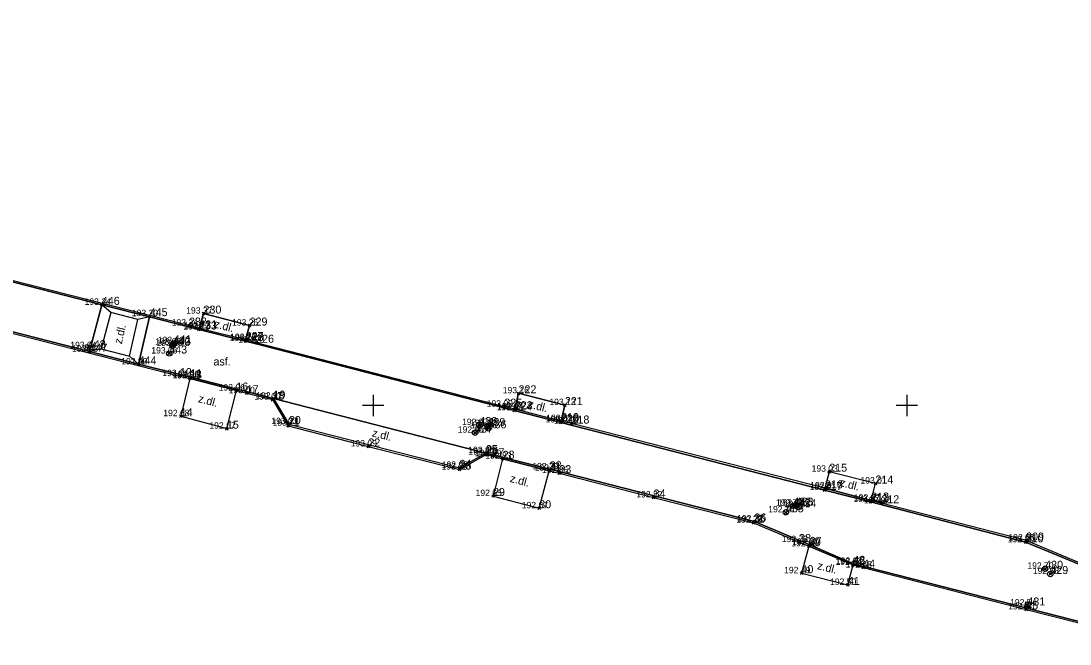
# Model space of a CAD drawing. Extents: x -706861 to -706379, y -1036456 to -1036201.
# Drawn here: x -706633 to -706534.7, y -1036372.3 to -1036314 of the extents above; entities that cross this region are included whole.
import ezdxf

# ---------------------------------------------------------------- set-up
doc = ezdxf.new("R2010")
doc.units = 0
for name, color, linetype in [('18_popisy', 7, 'Continuous'), ('29_vodovod', 7, 'Continuous'), ('30_kanalizace splašková', 7, 'Continuous'), ('40_plochy', 7, 'Continuous'), ('51_body polohopisu_značky', 7, 'Continuous'), ('52_body polohopisu_čísla', 7, 'Continuous'), ('53_body polohopisu_výšky', 7, 'Continuous'), ('54_body polohopisu_čísla nadbytečné pro kreslení', 7, 'Continuous'), ('5_rozhraní ploch', 7, 'Continuous'), ('60_mapový rám_legenda', 7, 'Continuous')]:
    doc.layers.add(name, color=color, linetype=linetype)

msp = doc.modelspace()

# ---------------------------------------------------------------- linework, layer by layer
at = {"layer": '29_vodovod'}
for centre in [(-706618.79, -1036344.42), (-706618.67, -1036344.15), (-706590.05, -1036351.82), (-706589.29, -1036351.91), (-706560.65, -1036359.38), (-706560.43, -1036359.38), (-706537.05, -1036365.29)]:
    msp.add_circle(centre, 0.25, dxfattribs=at)
at = {"layer": '30_kanalizace splašková'}
for p, q in [((-706626.661, -1036344.377), (-706626.779, -1036344.863)), ((-706538.657, -1036368.488), (-706538.783, -1036368.972))]:
    msp.add_line(p, q, dxfattribs=at)
for points in [[(-706626.904, -1036344.318), (-706627.023, -1036344.804), (-706626.536, -1036344.923), (-706626.417, -1036344.437)], [(-706538.9, -1036368.425), (-706539.026, -1036368.909), (-706538.54, -1036369.035), (-706538.415, -1036368.551)]]:
    msp.add_lwpolyline(points, close=True, dxfattribs=at)
for centre in [(-706618.78, -1036344.3), (-706619.1, -1036345.12), (-706590.45, -1036352.54), (-706589.19, -1036352.13), (-706560.15, -1036359.52), (-706561.34, -1036360), (-706536.57, -1036365.78)]:
    msp.add_circle(centre, 0.25, dxfattribs=at)
at = {"layer": '40_plochy'}
for points in [[(-706673.91, -1036328.1), (-706669.56, -1036329.23), (-706644.87, -1036335.59), (-706640.53, -1036336.68), (-706625.407, -1036340.547), (-706626.555, -1036344.932), (-706641.34, -1036341.16), (-706645.7, -1036340.05), (-706670.86, -1036333.6), (-706675.27, -1036332.47)], [(-706625.407, -1036340.547), (-706620.945, -1036341.687), (-706621.962, -1036346.105), (-706626.555, -1036344.932)], [(-706615.89, -1036341.38), (-706611.57, -1036342.5), (-706611.94, -1036343.85), (-706616.28, -1036342.77)], [(-706617.16, -1036347.46), (-706618.02, -1036350.99), (-706613.7, -1036352.16), (-706612.81, -1036348.59)], [(-706609.33, -1036349.34), (-706607.89, -1036351.73), (-706591.92, -1036355.83), (-706589.44, -1036354.45)], [(-706586.38, -1036348.85), (-706582.04, -1036349.95), (-706582.39, -1036351.45), (-706586.73, -1036350.34)], [(-706587.87, -1036354.98), (-706588.77, -1036358.47), (-706584.44, -1036359.62), (-706583.5, -1036356.1)], [(-706557.28, -1036356.19), (-706557.68, -1036357.75), (-706553.35, -1036358.9), (-706552.95, -1036357.3)], [(-706559.18, -1036363.18), (-706559.88, -1036365.71), (-706555.53, -1036366.8), (-706555.05, -1036364.92)]]:
    msp.add_lwpolyline(points, close=True, dxfattribs=at)
msp.add_lwpolyline([(-706530.33, -1036371.14), (-706555.02, -1036364.83), (-706559.11, -1036363.05), (-706564.29, -1036360.86), (-706583.46, -1036355.97), (-706589.44, -1036354.45), (-706609.33, -1036349.34), (-706617.12, -1036347.34), (-706621.962, -1036346.105), (-706620.945, -1036341.687), (-706616.32, -1036342.87), (-706611.97, -1036343.95), (-706610.97, -1036344.21), (-706586.78, -1036350.45), (-706582.43, -1036351.58), (-706557.72, -1036357.91), (-706553.4, -1036359.02), (-706538.88, -1036362.81), (-706529.64, -1036366.62)], dxfattribs=at)
at = {"layer": '51_body polohopisu_značky'}
for points in [[(-706625.53, -1036340.68), (-706625.29, -1036340.44)], [(-706625.53, -1036340.44), (-706625.29, -1036340.68)], [(-706621.05, -1036341.74), (-706620.81, -1036341.5)], [(-706621.05, -1036341.5), (-706620.81, -1036341.74)], [(-706616.01, -1036341.5), (-706615.77, -1036341.26)], [(-706616.01, -1036341.26), (-706615.77, -1036341.5)], [(-706617.37, -1036342.62), (-706617.13, -1036342.38)], [(-706617.37, -1036342.38), (-706617.13, -1036342.62)], [(-706611.69, -1036342.62), (-706611.45, -1036342.38)], [(-706611.69, -1036342.38), (-706611.45, -1036342.62)], [(-706616.44, -1036342.99), (-706616.2, -1036342.75)], [(-706616.44, -1036342.75), (-706616.2, -1036342.99)], [(-706616.4, -1036342.89), (-706616.16, -1036342.65)], [(-706616.4, -1036342.65), (-706616.16, -1036342.89)], [(-706626.84, -1036344.74), (-706626.6, -1036344.5)], [(-706626.84, -1036344.5), (-706626.6, -1036344.74)], [(-706618.91, -1036344.54), (-706618.67, -1036344.3)], [(-706618.91, -1036344.3), (-706618.67, -1036344.54)], [(-706618.9, -1036344.42), (-706618.66, -1036344.18)], [(-706618.9, -1036344.18), (-706618.66, -1036344.42)], [(-706618.79, -1036344.27), (-706618.55, -1036344.03)], [(-706618.79, -1036344.03), (-706618.55, -1036344.27)], [(-706612.06, -1036343.97), (-706611.82, -1036343.73)], [(-706612.06, -1036343.73), (-706611.82, -1036343.97)], [(-706612.06, -1036344.07), (-706611.82, -1036343.83)], [(-706612.06, -1036343.83), (-706611.82, -1036344.07)], [(-706611.08, -1036344.23), (-706610.84, -1036343.99)], [(-706611.08, -1036343.99), (-706610.84, -1036344.23)], [(-706626.68, -1036345.07), (-706626.44, -1036344.83)], [(-706626.68, -1036344.83), (-706626.44, -1036345.07)], [(-706619.22, -1036345.24), (-706618.98, -1036345)], [(-706619.22, -1036345), (-706618.98, -1036345.24)], [(-706622.09, -1036346.26), (-706621.85, -1036346.02)], [(-706622.09, -1036346.02), (-706621.85, -1036346.26)], [(-706618.22, -1036347.36), (-706617.98, -1036347.12)], [(-706618.22, -1036347.12), (-706617.98, -1036347.36)], [(-706617.28, -1036347.58), (-706617.04, -1036347.34)], [(-706617.28, -1036347.34), (-706617.04, -1036347.58)], [(-706617.24, -1036347.46), (-706617, -1036347.22)], [(-706617.24, -1036347.22), (-706617, -1036347.46)], [(-706612.93, -1036348.71), (-706612.69, -1036348.47)], [(-706612.93, -1036348.47), (-706612.69, -1036348.71)], [(-706611.96, -1036348.96), (-706611.72, -1036348.72)], [(-706611.96, -1036348.72), (-706611.72, -1036348.96)], [(-706609.54, -1036349.56), (-706609.3, -1036349.32)], [(-706609.54, -1036349.32), (-706609.3, -1036349.56)], [(-706609.45, -1036349.46), (-706609.21, -1036349.22)], [(-706609.45, -1036349.22), (-706609.21, -1036349.46)], [(-706586.5, -1036348.97), (-706586.26, -1036348.73)], [(-706586.5, -1036348.73), (-706586.26, -1036348.97)], [(-706587.83, -1036350.22), (-706587.59, -1036349.98)], [(-706587.83, -1036349.98), (-706587.59, -1036350.22)], [(-706586.9, -1036350.57), (-706586.66, -1036350.33)], [(-706586.9, -1036350.33), (-706586.66, -1036350.57)], [(-706586.85, -1036350.46), (-706586.61, -1036350.22)], [(-706586.85, -1036350.22), (-706586.61, -1036350.46)], [(-706582.16, -1036350.07), (-706581.92, -1036349.83)], [(-706582.16, -1036349.83), (-706581.92, -1036350.07)], [(-706618.14, -1036351.11), (-706617.9, -1036350.87)], [(-706618.14, -1036350.87), (-706617.9, -1036351.11)], [(-706582.51, -1036351.57), (-706582.27, -1036351.33)], [(-706582.51, -1036351.33), (-706582.27, -1036351.57)], [(-706613.82, -1036352.28), (-706613.58, -1036352.04)], [(-706613.82, -1036352.04), (-706613.58, -1036352.28)], [(-706608.09, -1036352.01), (-706607.85, -1036351.77)], [(-706608.09, -1036351.77), (-706607.85, -1036352.01)], [(-706608.01, -1036351.85), (-706607.77, -1036351.61)], [(-706608.01, -1036351.61), (-706607.77, -1036351.85)], [(-706590.57, -1036352.66), (-706590.33, -1036352.42)], [(-706590.57, -1036352.42), (-706590.33, -1036352.66)], [(-706590.17, -1036351.94), (-706589.93, -1036351.7)], [(-706590.17, -1036351.7), (-706589.93, -1036351.94)], [(-706589.41, -1036352.03), (-706589.17, -1036351.79)], [(-706589.41, -1036351.79), (-706589.17, -1036352.03)], [(-706589.31, -1036352.25), (-706589.07, -1036352.01)], [(-706589.31, -1036352.01), (-706589.07, -1036352.25)], [(-706582.55, -1036351.7), (-706582.31, -1036351.46)], [(-706582.55, -1036351.46), (-706582.31, -1036351.7)], [(-706581.54, -1036351.8), (-706581.3, -1036351.56)], [(-706581.54, -1036351.56), (-706581.3, -1036351.8)], [(-706600.57, -1036353.95), (-706600.33, -1036353.71)], [(-706600.57, -1036353.71), (-706600.33, -1036353.95)], [(-706589.56, -1036354.57), (-706589.32, -1036354.33)], [(-706589.56, -1036354.33), (-706589.32, -1036354.57)], [(-706589.52, -1036354.71), (-706589.28, -1036354.47)], [(-706589.52, -1036354.47), (-706589.28, -1036354.71)], [(-706588.94, -1036354.86), (-706588.7, -1036354.62)], [(-706588.94, -1036354.62), (-706588.7, -1036354.86)], [(-706587.99, -1036355.1), (-706587.75, -1036354.86)], [(-706587.99, -1036354.86), (-706587.75, -1036355.1)], [(-706592.04, -1036355.95), (-706591.8, -1036355.71)], [(-706592.04, -1036355.71), (-706591.8, -1036355.95)], [(-706592.03, -1036356.11), (-706591.79, -1036355.87)], [(-706592.03, -1036355.87), (-706591.79, -1036356.11)], [(-706583.62, -1036356.22), (-706583.38, -1036355.98)], [(-706583.62, -1036355.98), (-706583.38, -1036356.22)], [(-706583.58, -1036356.09), (-706583.34, -1036355.85)], [(-706583.58, -1036355.85), (-706583.34, -1036356.09)], [(-706582.68, -1036356.45), (-706582.44, -1036356.21)], [(-706582.68, -1036356.21), (-706582.44, -1036356.45)], [(-706557.4, -1036356.31), (-706557.16, -1036356.07)], [(-706557.4, -1036356.07), (-706557.16, -1036356.31)], [(-706553.07, -1036357.42), (-706552.83, -1036357.18)], [(-706553.07, -1036357.18), (-706552.83, -1036357.42)], [(-706557.84, -1036358.03), (-706557.6, -1036357.79)], [(-706557.84, -1036357.79), (-706557.6, -1036358.03)], [(-706557.8, -1036357.87), (-706557.56, -1036357.63)], [(-706557.8, -1036357.63), (-706557.56, -1036357.87)], [(-706588.89, -1036358.59), (-706588.65, -1036358.35)], [(-706588.89, -1036358.35), (-706588.65, -1036358.59)], [(-706573.85, -1036358.73), (-706573.61, -1036358.49)], [(-706573.85, -1036358.49), (-706573.61, -1036358.73)], [(-706560.77, -1036359.5), (-706560.53, -1036359.26)], [(-706560.77, -1036359.26), (-706560.53, -1036359.5)], [(-706560.55, -1036359.5), (-706560.31, -1036359.26)], [(-706560.55, -1036359.26), (-706560.31, -1036359.5)], [(-706553.52, -1036359.14), (-706553.28, -1036358.9)], [(-706553.52, -1036358.9), (-706553.28, -1036359.14)], [(-706553.47, -1036359.02), (-706553.23, -1036358.78)], [(-706553.47, -1036358.78), (-706553.23, -1036359.02)], [(-706552.52, -1036359.27), (-706552.28, -1036359.03)], [(-706552.52, -1036359.03), (-706552.28, -1036359.27)], [(-706584.56, -1036359.74), (-706584.32, -1036359.5)], [(-706584.56, -1036359.5), (-706584.32, -1036359.74)], [(-706561.46, -1036360.12), (-706561.22, -1036359.88)], [(-706561.46, -1036359.88), (-706561.22, -1036360.12)], [(-706560.27, -1036359.64), (-706560.03, -1036359.4)], [(-706560.27, -1036359.4), (-706560.03, -1036359.64)], [(-706564.49, -1036361.09), (-706564.25, -1036360.85)], [(-706564.49, -1036360.85), (-706564.25, -1036361.09)], [(-706564.41, -1036360.98), (-706564.17, -1036360.74)], [(-706564.41, -1036360.74), (-706564.17, -1036360.98)], [(-706560.22, -1036362.91), (-706559.98, -1036362.67)], [(-706560.22, -1036362.67), (-706559.98, -1036362.91)], [(-706559.3, -1036363.3), (-706559.06, -1036363.06)], [(-706559.3, -1036363.06), (-706559.06, -1036363.3)], [(-706559.23, -1036363.17), (-706558.99, -1036362.93)], [(-706559.23, -1036362.93), (-706558.99, -1036363.17)], [(-706539, -1036362.93), (-706538.76, -1036362.69)], [(-706539, -1036362.69), (-706538.76, -1036362.93)], [(-706538.96, -1036362.76), (-706538.72, -1036362.52)], [(-706538.96, -1036362.52), (-706538.72, -1036362.76)], [(-706555.17, -1036365.04), (-706554.93, -1036364.8)], [(-706555.17, -1036364.8), (-706554.93, -1036365.04)], [(-706555.14, -1036364.95), (-706554.9, -1036364.71)], [(-706555.14, -1036364.71), (-706554.9, -1036364.95)], [(-706554.22, -1036365.29), (-706553.98, -1036365.05)], [(-706554.22, -1036365.05), (-706553.98, -1036365.29)], [(-706537.17, -1036365.41), (-706536.93, -1036365.17)], [(-706537.17, -1036365.17), (-706536.93, -1036365.41)], [(-706560, -1036365.83), (-706559.76, -1036365.59)], [(-706560, -1036365.59), (-706559.76, -1036365.83)], [(-706536.69, -1036365.9), (-706536.45, -1036365.66)], [(-706536.69, -1036365.66), (-706536.45, -1036365.9)], [(-706555.65, -1036366.92), (-706555.41, -1036366.68)], [(-706555.65, -1036366.68), (-706555.41, -1036366.92)], [(-706538.95, -1036369.22), (-706538.71, -1036368.98)], [(-706538.95, -1036368.98), (-706538.71, -1036369.22)], [(-706538.84, -1036368.85), (-706538.6, -1036368.61)], [(-706538.84, -1036368.61), (-706538.6, -1036368.85)]]:
    msp.add_lwpolyline(points, dxfattribs=at)
at = {"layer": '5_rozhraní ploch'}
for p, q in [((-706624.564, -1036341.278), (-706625.407, -1036340.547)), ((-706620.945, -1036341.687), (-706622.027, -1036341.927)), ((-706625.46, -1036344.696), (-706626.555, -1036344.932)), ((-706622.819, -1036345.37), (-706621.962, -1036346.105))]:
    msp.add_line(p, q, dxfattribs=at)
for points in [[(-706611.97, -1036343.95), (-706616.32, -1036342.87), (-706620.945, -1036341.687), (-706625.407, -1036340.547), (-706640.53, -1036336.68), (-706644.87, -1036335.59), (-706669.56, -1036329.23), (-706673.91, -1036328.1), (-706684.54, -1036325.41), (-706703.07, -1036320.63), (-706706.65, -1036319.75), (-706716.69, -1036318.74), (-706728.29, -1036315.81), (-706732.59, -1036314.76), (-706736.58, -1036313.96)], [(-706670.86, -1036333.6), (-706654.96, -1036337.67), (-706645.7, -1036340.05), (-706641.34, -1036341.16), (-706626.555, -1036344.932), (-706621.962, -1036346.105), (-706617.12, -1036347.34), (-706609.33, -1036349.34), (-706607.89, -1036351.73), (-706591.92, -1036355.83), (-706589.44, -1036354.45), (-706583.46, -1036355.97), (-706564.29, -1036360.86), (-706559.11, -1036363.05), (-706555.02, -1036364.83), (-706530.33, -1036371.14), (-706525.95, -1036372.11), (-706524.99, -1036372.34)], [(-706518.9, -1036367), (-706521.32, -1036368.51), (-706525.29, -1036367.55), (-706529.63, -1036366.53), (-706530.5, -1036366.13), (-706538.84, -1036362.64), (-706552.4, -1036359.15), (-706553.35, -1036358.9), (-706557.68, -1036357.75), (-706581.42, -1036351.68), (-706582.39, -1036351.45), (-706586.73, -1036350.34), (-706587.71, -1036350.1), (-706610.95, -1036344.11), (-706611.94, -1036343.85), (-706616.28, -1036342.77), (-706617.25, -1036342.5), (-706639.52, -1036336.83)], [(-706625.407, -1036340.547), (-706626.555, -1036344.932)], [(-706640.42, -1036341.53), (-706618.1, -1036347.24), (-706617.16, -1036347.46), (-706612.81, -1036348.59), (-706611.84, -1036348.84), (-706609.42, -1036349.44), (-706607.97, -1036351.89), (-706600.45, -1036353.83), (-706591.91, -1036355.99), (-706589.4, -1036354.59), (-706588.82, -1036354.74), (-706587.87, -1036354.98), (-706583.5, -1036356.1), (-706582.56, -1036356.33), (-706573.73, -1036358.61), (-706564.37, -1036360.97), (-706560.1, -1036362.79), (-706559.18, -1036363.18), (-706555.05, -1036364.92), (-706554.1, -1036365.17), (-706538.83, -1036369.1), (-706531.32, -1036371.01)], [(-706624.564, -1036341.278), (-706625.46, -1036344.696)], [(-706622.027, -1036341.927), (-706624.564, -1036341.278)], [(-706611.94, -1036343.85), (-706611.57, -1036342.5), (-706615.89, -1036341.38), (-706616.28, -1036342.77)], [(-706622.819, -1036345.37), (-706622.027, -1036341.927)], [(-706621.962, -1036346.105), (-706620.945, -1036341.687)], [(-706518.86, -1036367.15), (-706521.26, -1036368.67), (-706525.27, -1036367.7), (-706529.64, -1036366.62), (-706538.88, -1036362.81), (-706553.4, -1036359.02), (-706557.72, -1036357.91), (-706582.43, -1036351.58), (-706586.78, -1036350.45), (-706610.97, -1036344.21), (-706611.97, -1036343.95)], [(-706625.46, -1036344.696), (-706622.819, -1036345.37)], [(-706617.16, -1036347.46), (-706618.02, -1036350.99), (-706613.7, -1036352.16), (-706612.81, -1036348.59)], [(-706609.33, -1036349.34), (-706589.44, -1036354.45)], [(-706582.39, -1036351.45), (-706582.04, -1036349.95), (-706586.38, -1036348.85), (-706586.73, -1036350.34)], [(-706587.87, -1036354.98), (-706588.77, -1036358.47), (-706584.44, -1036359.62), (-706583.5, -1036356.1)], [(-706553.35, -1036358.9), (-706552.95, -1036357.3), (-706557.28, -1036356.19), (-706557.68, -1036357.75)], [(-706559.18, -1036363.18), (-706559.88, -1036365.71), (-706555.53, -1036366.8), (-706555.05, -1036364.92)]]:
    msp.add_lwpolyline(points, dxfattribs=at)
at = {"layer": '60_mapový rám_legenda'}
for points in [[(-706600, -1036349), (-706600, -1036350), (-706600, -1036351)], [(-706550, -1036349), (-706550, -1036350), (-706550, -1036351)], [(-706599, -1036350), (-706600, -1036350), (-706601, -1036350)], [(-706549, -1036350), (-706550, -1036350), (-706551, -1036350)]]:
    msp.add_lwpolyline(points, dxfattribs=at)

# ---------------------------------------------------------------- texts
at = {"layer": '18_popisy'}
for rotation, p in [(77.04242, (-706623.55, -1036344.281)), (345.46554, (-706614.932, -1036342.667)), (344.84593, (-706616.439, -1036349.662)), (345.77753, (-706585.539, -1036350.176)), (345.806, (-706600.151, -1036352.874)), (345.12625, (-706587.237, -1036357.138)), (345.62179, (-706556.337, -1036357.522)), (345.93277, (-706558.445, -1036365.311))]:
    msp.add_text('z.dl.', height=0.75, rotation=rotation, dxfattribs=at).set_placement(p)
msp.add_text('asf.', height=0.75, dxfattribs=at).set_placement((-706614.95, -1036346.24))
at = {"layer": '52_body polohopisu_čísla'}
for s, p in [('446', (-706625.41, -1036340.56)), ('230', (-706615.89, -1036341.38)), ('445', (-706620.93, -1036341.62)), ('229', (-706611.57, -1036342.5)), ('228', (-706611.94, -1036343.95)), ('447', (-706626.56, -1036344.95)), ('440', (-706618.79, -1036344.42)), ('444', (-706621.97, -1036346.14)), ('12', (-706618.1, -1036347.24)), ('16', (-706612.81, -1036348.59)), ('17', (-706611.84, -1036348.84)), ('19', (-706609.33, -1036349.34)), ('221', (-706582.04, -1036349.95)), ('14', (-706618.02, -1036350.99)), ('15', (-706613.7, -1036352.16)), ('21', (-706607.97, -1036351.89)), ('219', (-706582.39, -1036351.45)), ('437', (-706590.45, -1036352.54)), ('22', (-706600.45, -1036353.83)), ('26', (-706589.4, -1036354.59)), ('28', (-706587.87, -1036354.98)), ('24', (-706591.92, -1036355.83)), ('31', (-706583.5, -1036356.1)), ('33', (-706582.56, -1036356.33)), ('215', (-706557.28, -1036356.19)), ('214', (-706552.95, -1036357.3)), ('29', (-706588.77, -1036358.47)), ('34', (-706573.73, -1036358.61)), ('213', (-706553.35, -1036358.9)), ('30', (-706584.44, -1036359.62)), ('435', (-706561.34, -1036360)), ('35', (-706564.37, -1036360.97)), ('210', (-706538.88, -1036362.81)), ('37', (-706559.11, -1036363.05)), ('40', (-706559.88, -1036365.71)), ('44', (-706554.1, -1036365.17)), ('429', (-706536.57, -1036365.78)), ('41', (-706555.53, -1036366.8)), ('45', (-706538.83, -1036369.1))]:
    msp.add_text(s, height=0.75, dxfattribs=at).set_placement(p)
at = {"layer": '53_body polohopisu_výšky'}
for s, p in [('193 24 ', (-706627.028, -1036340.56)), ('193 20 ', (-706622.6, -1036341.62)), ('193 37 ', (-706617.508, -1036341.38)), ('193 24 ', (-706618.868, -1036342.5)), ('193 17 ', (-706617.768, -1036342.87)), ('193 17 ', (-706617.728, -1036342.77)), ('193 26 ', (-706613.221, -1036342.5)), ('193 10 ', (-706620.17, -1036344.15)), ('193 16 ', (-706613.421, -1036343.95)), ('193 15 ', (-706613.388, -1036343.85)), ('193 20 ', (-706612.63, -1036344.11)), ('193 04 ', (-706628.364, -1036344.62)), ('193 03 ', (-706628.204, -1036344.95)), ('193 06 ', (-706620.777, -1036345.12)), ('193 09 ', (-706620.429, -1036344.3)), ('193 10 ', (-706620.29, -1036344.42)), ('192 99 ', (-706623.595, -1036346.14)), ('193 04 ', (-706619.744, -1036347.24)), ('192 98 ', (-706618.78, -1036347.46)), ('192 98 ', (-706618.74, -1036347.34)), ('192 96 ', (-706614.463, -1036348.59)), ('193 00 ', (-706613.536, -1036348.84)), ('193 16 ', (-706587.861, -1036348.85)), ('193 00 ', (-706611.116, -1036349.44)), ('192 97 ', (-706610.95, -1036349.34)), ('193 13 ', (-706583.488, -1036349.95)), ('192 68 ', (-706619.655, -1036350.99)), ('193 09 ', (-706589.359, -1036350.1)), ('193 03 ', (-706588.424, -1036350.45)), ('193 04 ', (-706588.374, -1036350.34)), ('193 03 ', (-706609.534, -1036351.73)), ('193 14 ', (-706609.418, -1036351.89)), ('192 97 ', (-706591.67, -1036351.82)), ('192 97 ', (-706590.91, -1036351.91)), ('193 01 ', (-706583.833, -1036351.58)), ('193 01 ', (-706583.793, -1036351.45)), ('193 07 ', (-706583.064, -1036351.68)), ('192 67 ', (-706615.335, -1036352.16)), ('192 95 ', (-706592.07, -1036352.54)), ('192 96 ', (-706590.843, -1036352.13)), ('193 09 ', (-706602.099, -1036353.83)), ('192 86 ', (-706591.091, -1036354.45)), ('192 90 ', (-706591.072, -1036354.59)), ('192 89 ', (-706590.443, -1036354.74)), ('192 83 ', (-706589.488, -1036354.98)), ('193 06 ', (-706593.587, -1036355.99)), ('192 96 ', (-706593.573, -1036355.83)), ('192 79 ', (-706585.083, -1036355.97)), ('192 81 ', (-706584.877, -1036356.1)), ('192 85 ', (-706584.178, -1036356.33)), ('193 03 ', (-706558.924, -1036356.19)), ('192 91 ', (-706559.099, -1036357.91)), ('192 91 ', (-706559.059, -1036357.75)), ('193 01 ', (-706554.353, -1036357.3)), ('192 65 ', (-706590.405, -1036358.47)), ('192 82 ', (-706575.348, -1036358.61)), ('192 87 ', (-706554.968, -1036358.9)), ('192 67 ', (-706586.075, -1036359.62)), ('192 78 ', (-706562.268, -1036359.38)), ('192 80 ', (-706562.1, -1036359.38)), ('192 81 ', (-706561.527, -1036359.52)), ('192 87 ', (-706555.018, -1036359.02)), ('192 92 ', (-706554.02, -1036359.15)), ('192 72 ', (-706565.908, -1036360.86)), ('192 76 ', (-706562.991, -1036360)), ('192 78 ', (-706565.988, -1036360.97)), ('192 73 ', (-706561.718, -1036362.79)), ('192 80 ', (-706540.55, -1036362.81)), ('192 86 ', (-706540.491, -1036362.64)), ('192 68 ', (-706560.815, -1036363.18)), ('192 67 ', (-706560.745, -1036363.05)), ('192 63 ', (-706556.655, -1036364.83)), ('192 49 ', (-706561.503, -1036365.71)), ('192 64 ', (-706556.685, -1036364.92)), ('192 68 ', (-706555.735, -1036365.17)), ('192 70 ', (-706538.72, -1036365.29)), ('192 68 ', (-706538.205, -1036365.78)), ('192 50 ', (-706557.2, -1036366.8)), ('192 54 ', (-706540.338, -1036368.73)), ('192 60 ', (-706540.516, -1036369.1))]:
    msp.add_text(s, height=0.6, dxfattribs=at).set_placement(p)
at = {"layer": '54_body polohopisu_čísla nadbytečné pro kreslení'}
for s, p in [('232', (-706617.25, -1036342.5)), ('233', (-706616.32, -1036342.87)), ('231', (-706616.28, -1036342.77)), ('442', (-706618.78, -1036344.3)), ('441', (-706618.67, -1036344.15)), ('227', (-706611.94, -1036343.85)), ('226', (-706610.96, -1036344.11)), ('448', (-706626.72, -1036344.62)), ('443', (-706619.1, -1036345.12)), ('13', (-706617.16, -1036347.46)), ('11', (-706617.12, -1036347.34)), ('222', (-706586.38, -1036348.85)), ('18', (-706609.42, -1036349.44)), ('225', (-706587.71, -1036350.1)), ('224', (-706586.78, -1036350.45)), ('223', (-706586.73, -1036350.34)), ('20', (-706607.89, -1036351.73)), ('438', (-706590.05, -1036351.82)), ('439', (-706589.29, -1036351.91)), ('436', (-706589.19, -1036352.13)), ('220', (-706582.43, -1036351.58)), ('218', (-706581.42, -1036351.68)), ('25', (-706589.44, -1036354.45)), ('27', (-706588.82, -1036354.74)), ('23', (-706591.91, -1036355.99)), ('32', (-706583.46, -1036355.97)), ('217', (-706557.72, -1036357.91)), ('216', (-706557.68, -1036357.75)), ('211', (-706553.4, -1036359.02)), ('432', (-706560.65, -1036359.38)), ('433', (-706560.43, -1036359.38)), ('434', (-706560.15, -1036359.52)), ('212', (-706552.4, -1036359.15)), ('36', (-706564.29, -1036360.86)), ('38', (-706560.1, -1036362.79)), ('209', (-706538.84, -1036362.64)), ('39', (-706559.18, -1036363.18)), ('42', (-706555.05, -1036364.92)), ('43', (-706555.02, -1036364.83)), ('430', (-706537.05, -1036365.29)), ('431', (-706538.72, -1036368.73))]:
    msp.add_text(s, height=0.75, dxfattribs=at).set_placement(p)

doc.saveas('drawing.dxf')
